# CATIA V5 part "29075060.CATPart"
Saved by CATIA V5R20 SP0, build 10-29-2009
Part number: 29075060
Definition: NONE
Nomenclature: 29075060
Source: Unknown
Description: 29075060
Bounding box of the stored display mesh (mm): x -30 to 44.548, y -51.5 to 86.048, z -41.5 to 41.5
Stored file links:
  C:\Users\Utente\Desktop\IO LAVORO\3D X SITO CF\X SITO\PLASTICA\RF1\29075060.CATPart
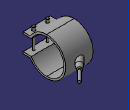
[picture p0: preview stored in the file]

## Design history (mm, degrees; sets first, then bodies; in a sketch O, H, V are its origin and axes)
Body1 "29075060" (main body)
  Solid1: solid without history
